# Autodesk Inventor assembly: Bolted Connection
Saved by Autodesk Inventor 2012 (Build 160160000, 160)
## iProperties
Created: 2010-12
Part Number: Bolted Connection
Document SubType Name: Assembly
Designer: Thom Tremblay
ClientObjectVersion: 1
Author: Thom Tremblay
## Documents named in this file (3)
- C:\Users\VMuser\Desktop\Inventor 2012 Essentials\Assemblies\Chapter 6\c6-01\Design Accelerator\Bolted Connection4.iam
- C:\Users\VMuser\Desktop\Inventor 2012 Essentials\Content Center Files\en-US\ISO 7091\ISO 7091 - ST 4 - 100 HV.ipt
- C:\Users\VMuser\Desktop\Inventor 2012 Essentials\Content Center Files\en-US\ISO 4017\ISO 4017 - M4 x 8ISO.ipt
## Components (2 placed, 2 different names)
1. ISO 7091 ST 4 - 100 HV:1
2. ISO 4017 M4 x 8:1
